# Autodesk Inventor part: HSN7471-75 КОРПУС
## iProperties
Created: 2011-02
Part Number: HSN7471-75 КОРПУС
Document SubType Name: Modeling
Designer: Чернышев Юрий
Mass: 46875.8 g
Surface Area: 12757.3 cm^2
Volume: 46875.8 cm^3
Density: 1 g/cm^3
Author: Чернышев Юрий
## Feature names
1. ExtrusionBlind1
2. ExtrusionBlind2
3. SweepPathOnly1
4. Loft1
5. Fillet1
6. ExtrusionBlind5
7. RevolutionAngle1
8. Fillet14
9. RectangularPattern1
10. RevolutionAngle3
11. RevolutionAngle2
12. Fillet15
13. RevolutionAngle4
14. Fillet20
15. Fillet21
16. Fillet22
17. ExtrusionBlind13
18. Fillet24
19. ExtrusionToPlane2
20. ExtrusionToPlane3
21. ExtrusionBlind12
22. ExtrusionToPlane4
23. ExtrusionToPlane5
24. ExtrusionBlind14
25. ExtrusionToPlane6
26. ExtrusionToPlane7
27. ExtrusionBlind15
28. ExtrusionToPlane8
29. ExtrusionToPlane9
30. ExtrusionBlind6
31. Fillet37
32. Fillet38
33. ExtrusionBlind7
34. Fillet39
35. Fillet40
36. ExtrusionBlind8
37. Fillet41
38. Hole2
39. Hole3
40. RectangularPattern2
41. Hole1
42. ExtrusionBlind9
43. ExtrusionToPlane10
44. ExtrusionBlind10
45. Fillet42
46. Hole4
47. RectangularPattern3
48. ExtrusionBlind11
49. Fillet43
50. Fillet44
51. Fillet45
52. Fillet46
53. Fillet47
54. Fillet48
55. Fillet49
56. Fillet50
57. Fillet51
58. Fillet52
59. Fillet53
60. Fillet54
61. Fillet55
62. Hole5
63. ExtrusionThru1
64. Fillet56
65. Fillet57
66. ExtrusionBlind16
67. Hole6
68. Fillet59
69. Fillet60
70. Fillet61
71. Hole7
72. ExtrusionBlind17
